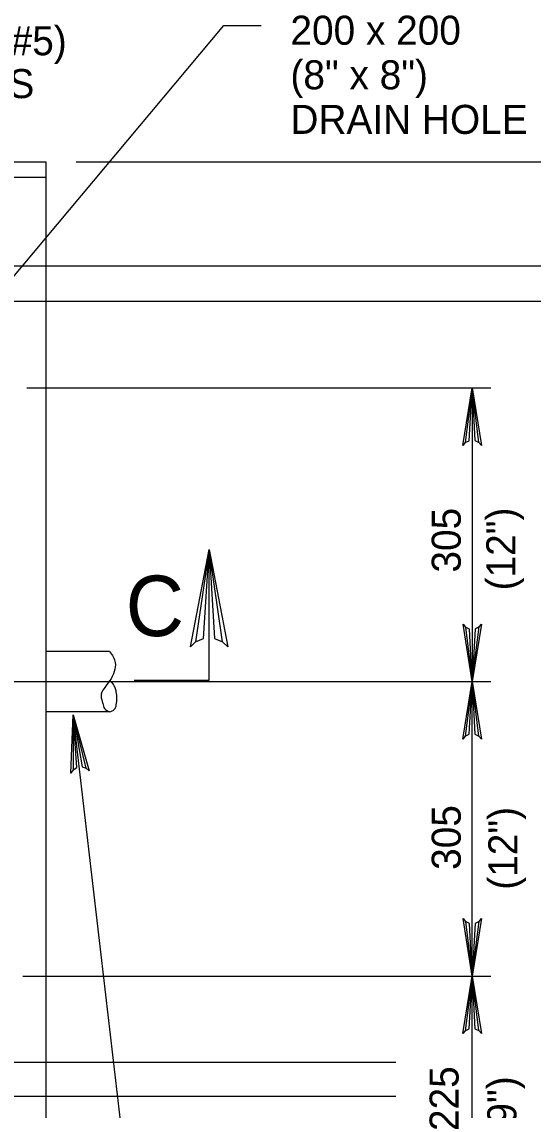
# Model space of a CAD drawing. Extents: x 638455 to 640199, y 298558 to 299152.
# Drawn here: x 639540.7 to 639600, y 298956 to 299082 of the extents above; entities that cross this region are included whole.
import ezdxf

# ---------------------------------------------------------------- set-up
doc = ezdxf.new("R2010")
doc.units = 0
for name, color, linetype in [('1', 7, 'Continuous'), ('2', 7, 'Continuous'), ('3', 7, 'Continuous')]:
    doc.layers.add(name, color=color, linetype=linetype)

msp = doc.modelspace()

# ---------------------------------------------------------------- linework, layer by layer
at = {"layer": '1'}
msp.add_line((639506.58, 299012.87), (639564.15, 299081.55), dxfattribs=at)
at = {"layer": '2'}
for p, q in [((639564.15, 299081.55), (639568.46, 299081.55)), ((639455.11, 299065.79), (639543.52, 299065.79)), ((639543.52, 299065.79), (639543.52, 298945.42)), ((639547.06, 299065.79), (639650.39, 299065.79)), ((639535.59, 299053.73), (639605.72, 299053.73)), ((639529.86, 299049.64), (639621, 299049.64)), ((639541.33, 299039.6), (639595.06, 299039.6)), ((639592.9, 299039.6), (639592.9, 299005.61)), ((639562.46, 299005.77), (639562.46, 299020.89)), ((639550.92, 299009.09), (639543.52, 299009.09)), ((639553.75, 299005.77), (639562.46, 299005.77)), ((639438.43, 299005.61), (639589.81, 299005.61)), ((639589.81, 299005.61), (639595.06, 299005.61)), ((639592.9, 298971.53), (639592.9, 299005.61)), ((639550.92, 299002.12), (639543.52, 299002.12)), ((639558.58, 298899.51), (639546.71, 299001.76)), ((639540.85, 298971.53), (639595.06, 298971.53)), ((639592.9, 298937.26), (639592.9, 298971.53)), ((639529.62, 298961.58), (639584.07, 298961.58)), ((639536.07, 298957.61), (639584.07, 298957.61))]:
    msp.add_line(p, q, dxfattribs=at)
for points in [[(639456.92, 299063.99), (639543.52, 299063.99)], [(639592.1, 299033.27), (639592.56, 299033.5), (639592.9, 299039.6), (639592.1, 299033.27), (639591.83, 299032.94), (639592.9, 299039.6), (639593.2, 299033.51), (639593.65, 299033.29), (639592.9, 299039.6), (639593.96, 299032.94), (639593.65, 299033.29)], [(639560.85, 299010.2), (639561.78, 299010.59), (639562.46, 299020.89), (639560.85, 299010.2), (639560.29, 299009.65), (639562.46, 299020.89), (639563.07, 299010.6), (639563.99, 299010.23), (639562.46, 299020.89), (639564.61, 299009.65), (639563.99, 299010.23)], [(639593.69, 299011.94), (639593.24, 299011.7), (639592.9, 299005.61), (639593.69, 299011.94), (639593.97, 299012.26), (639592.9, 299005.61), (639592.6, 299011.69), (639592.14, 299011.92), (639592.9, 299005.61), (639591.84, 299012.26), (639592.14, 299011.92)], [(639592.1, 298999.28), (639592.56, 298999.51), (639592.9, 299005.61), (639592.1, 298999.28), (639591.83, 298998.95), (639592.9, 299005.61), (639593.2, 298999.52), (639593.65, 298999.3), (639592.9, 299005.61), (639593.96, 298998.95), (639593.65, 298999.3)], [(639546.68, 298995.39), (639547.11, 298995.67), (639546.71, 299001.76), (639546.68, 298995.39), (639546.44, 298995.03), (639546.71, 299001.76), (639547.74, 298995.76), (639548.21, 298995.59), (639546.71, 299001.76), (639548.55, 298995.29), (639548.21, 298995.59)], [(639593.69, 298977.86), (639593.24, 298977.62), (639592.9, 298971.53), (639593.69, 298977.86), (639593.97, 298978.18), (639592.9, 298971.53), (639592.6, 298977.62), (639592.14, 298977.84), (639592.9, 298971.53), (639591.84, 298978.18), (639592.14, 298977.84)], [(639592.1, 298965.2), (639592.56, 298965.43), (639592.9, 298971.53), (639592.1, 298965.2), (639591.83, 298964.87), (639592.9, 298971.53), (639593.2, 298965.44), (639593.65, 298965.22), (639592.9, 298971.53), (639593.96, 298964.87), (639593.65, 298965.22)]]:
    msp.add_lwpolyline(points, dxfattribs=at)
for points in [[(639550.92, 299009.09), (639551.57, 299007.81), (639551.45, 299006.78), (639550.91, 299005.69), (639549.93, 299003.93), (639550.12, 299003.08), (639550.32, 299002.5), (639550.92, 299002.12)], [(639550.92, 299002.12), (639551.45, 299002.37), (639551.69, 299002.91), (639551.75, 299003.7), (639551.69, 299004.42), (639551.57, 299004.9), (639551.27, 299005.39), (639551.15, 299005.57), (639550.97, 299005.63)]]:
    msp.add_spline(points, degree=3, dxfattribs=at)

# ---------------------------------------------------------------- texts
at = {"layer": '1'}
for p in [(639597.89, 299016.17), (639598.13, 298981.52)]:
    msp.add_text('(12")', height=3.36, rotation=90, dxfattribs=at).set_placement(p)
at = {"layer": '3'}
for s, height, p in [('200 x 200', 3.36, (639571.85, 299079.33)), ('2-#16 (#5)', 3.36, (639525.22, 299078.11)), ('(8" x 8")', 3.36, (639571.85, 299074.17)), ('U-BARS', 3.36, (639525.22, 299073.15)), ('DRAIN HOLE', 3.36, (639571.85, 299069.01)), ('C', 7, (639552.77, 299010.88))]:
    msp.add_text(s, height=height, dxfattribs=at).set_placement(p)
for s, p in [('305', (639591.57, 299018.23)), ('305', (639591.57, 298983.82)), ('225', (639591.32, 298953.59)), ('(9")', (639598.01, 298952.84))]:
    msp.add_text(s, height=3.36, rotation=90, dxfattribs=at).set_placement(p)

doc.saveas('drawing.dxf')
